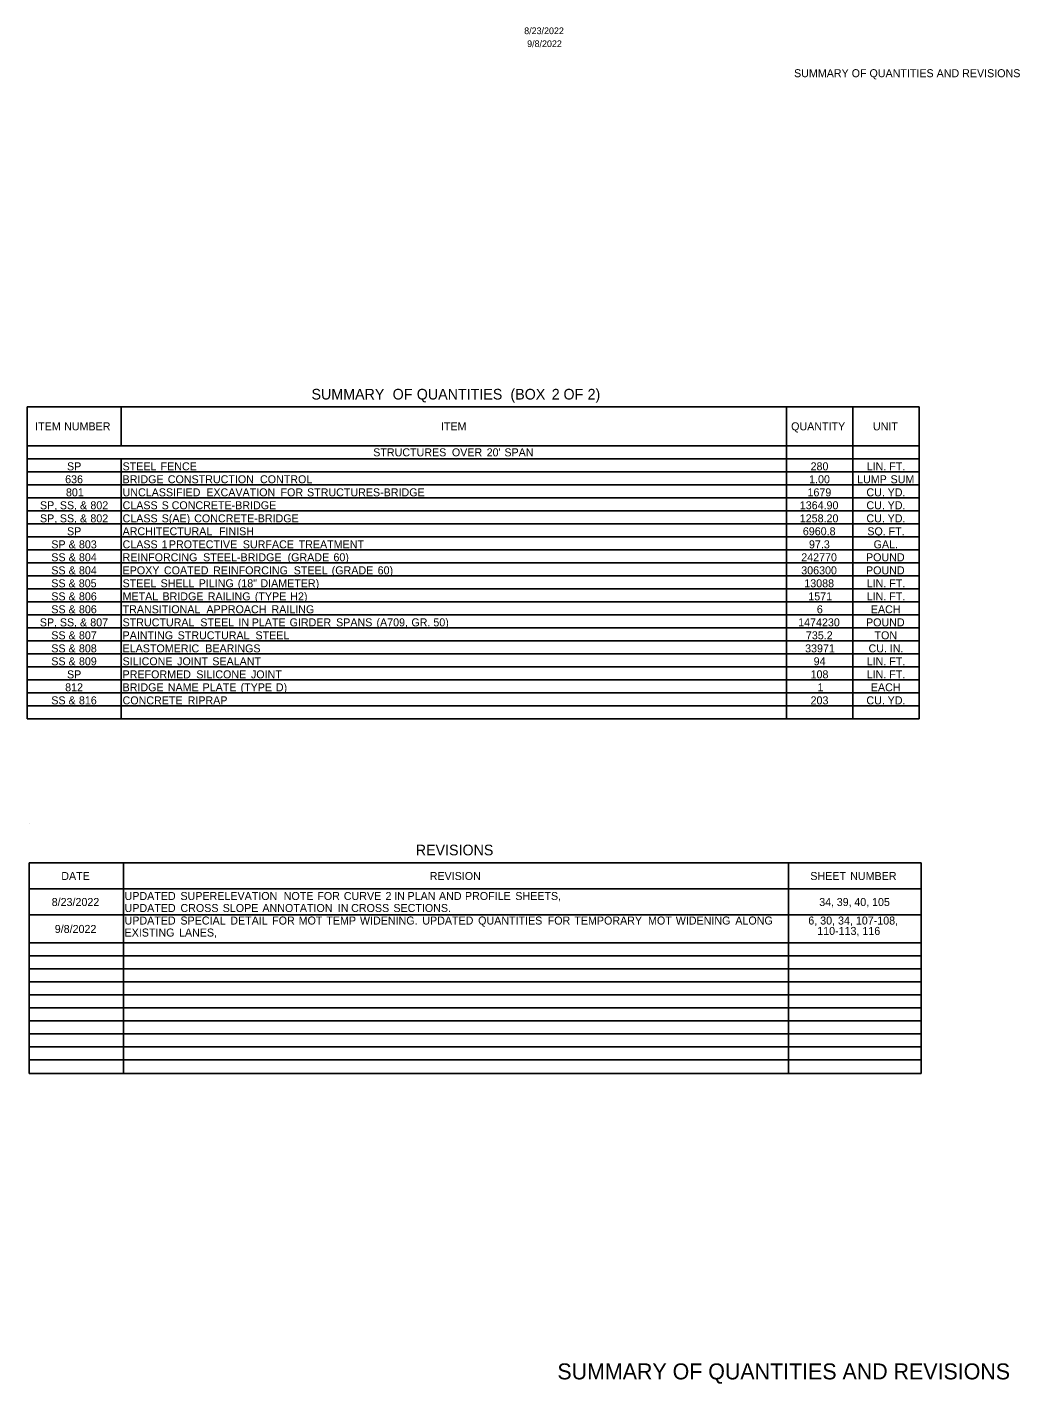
# Model space of a CAD drawing. Extents: x 1197542 to 1207068, y 230488 to 237324.
# Drawn here: x 1206323 to 1207068, y 231726 to 232744 of the extents above; entities that cross this region are included whole.
import ezdxf

# ---------------------------------------------------------------- set-up
doc = ezdxf.new("R2010")
doc.units = 0
for name, color, linetype in [('Default', 7, 'Continuous'), ('R_Annotation', 7, 'Continuous'), ('R_Border', 7, 'Continuous')]:
    doc.layers.add(name, color=color, linetype=linetype)

msp = doc.modelspace()

# ---------------------------------------------------------------- linework, layer by layer
at = {"layer": 'Default'}
for p, q in [((1206323.2, 232458.8), (1206393.8, 232458.8)), ((1206323.2, 232458.8), (1206992.5, 232458.8)), ((1206323.2, 232224.8), (1206323.2, 232458.8)), ((1206323.2, 232224.8), (1206323.2, 232458.8)), ((1206393.8, 232429.5), (1206393.8, 232458.8)), ((1206893, 232224.8), (1206893, 232458.8)), ((1206942.8, 232224.8), (1206942.8, 232458.8)), ((1206942.8, 232429.5), (1206942.8, 232458.8)), ((1206992.5, 232224.8), (1206992.5, 232458.8)), ((1206323.2, 232429.5), (1206992.5, 232429.5)), ((1206323.2, 232419.8), (1206992.5, 232419.8)), ((1206323.2, 232419.8), (1206992.5, 232419.8)), ((1206393.8, 232224.8), (1206393.8, 232419.8)), ((1206893, 232224.8), (1206893, 232419.8)), ((1206942.8, 232224.8), (1206942.8, 232419.8)), ((1206992.5, 232224.8), (1206992.5, 232419.8)), ((1206323.2, 232410), (1206992.5, 232410)), ((1206323.2, 232400.3), (1206992.5, 232400.3)), ((1206323.2, 232390.5), (1206992.5, 232390.5)), ((1206323.2, 232380.8), (1206992.5, 232380.8)), ((1206323.2, 232371), (1206992.5, 232371)), ((1206323.2, 232361.3), (1206992.5, 232361.3)), ((1206323.2, 232351.5), (1206992.5, 232351.5)), ((1206323.2, 232341.8), (1206992.5, 232341.8)), ((1206323.2, 232332), (1206992.5, 232332)), ((1206323.2, 232322.3), (1206992.5, 232322.3)), ((1206323.2, 232312.5), (1206992.5, 232312.5)), ((1206323.2, 232302.8), (1206992.5, 232302.8)), ((1206323.2, 232293), (1206992.5, 232293)), ((1206323.2, 232283.3), (1206992.5, 232283.3)), ((1206323.2, 232273.5), (1206992.5, 232273.5)), ((1206323.2, 232263.8), (1206992.5, 232263.8)), ((1206323.2, 232254), (1206992.5, 232254)), ((1206323.2, 232244.3), (1206992.5, 232244.3)), ((1206323.2, 232234.5), (1206992.5, 232234.5)), ((1206323.2, 232224.8), (1206992.5, 232224.8)), ((1206324.7, 232146), (1206324.7, 232146)), ((1206324.7, 232116.8), (1206994, 232116.8)), ((1206324.7, 232116.8), (1206395.4, 232116.8)), ((1206324.7, 231958.8), (1206324.7, 232116.8)), ((1206395.4, 231958.8), (1206395.4, 232116.8)), ((1206894.6, 232116.8), (1206994, 232116.8)), ((1206894.6, 232097.3), (1206894.6, 232116.8)), ((1206894.6, 231958.8), (1206894.6, 232116.8)), ((1206994, 231958.8), (1206994, 232116.8)), ((1206994, 231958.8), (1206994, 232116.8)), ((1206324.7, 232097.3), (1206994, 232097.3)), ((1206324.7, 232077.8), (1206994, 232077.8)), ((1206324.7, 232056.8), (1206994, 232056.8)), ((1206324.7, 232047.1), (1206994, 232047.1)), ((1206324.7, 232037.3), (1206994, 232037.3)), ((1206324.7, 232027.6), (1206994, 232027.6)), ((1206324.7, 232017.8), (1206994, 232017.8)), ((1206324.7, 232008.1), (1206994, 232008.1)), ((1206324.7, 231998.3), (1206994, 231998.3)), ((1206324.7, 231988.6), (1206994, 231988.6)), ((1206324.7, 231978.8), (1206994, 231978.8)), ((1206324.7, 231969.1), (1206994, 231969.1)), ((1206324.7, 231958.8), (1206994, 231958.8))]:
    msp.add_line(p, q, dxfattribs=at)

# ---------------------------------------------------------------- texts
for s, height, p in [(' SUMMARY', 8, (1206533.6, 232464.3)), (' OF', 8, (1206594.5, 232464.3)), (' QUANTITIES', 8, (1206612.6, 232464.3)), (' (BOX', 8, (1206682.9, 232464.3)), (' 2', 8, (1206713.9, 232464.3)), (' OF', 8, (1206722.7, 232464.3)), (' 2)', 8, (1206740.8, 232464.3)), ('ITEM', 6, (1206329.2, 232441.2)), (' NUMBER', 6, (1206348.7, 232441.2)), ('ITEM', 6, (1206633.7, 232441.2)), ('QUANTITY', 6, (1206896.5, 232441.2)), ('UNIT', 6, (1206957.9, 232441.2)), ('STRUCTURES', 6, (1206582.9, 232421.7)), (' OVER', 6, (1206639.7, 232421.7)), (" 20'", 6, (1206665.8, 232421.7)), (' SPAN', 6, (1206679.1, 232421.7)), ('SP', 6, (1206353.1, 232411.2)), ('STEEL', 6, (1206394.8, 232411.2)), (' FENCE', 6, (1206421.1, 232411.2)), ('280', 6, (1206911.1, 232411.2)), ('LIN.', 6, (1206953.2, 232411.2)), (' FT.', 6, (1206967.9, 232411.2)), ('636', 6, (1206351.7, 232401.5)), ('BRIDGE', 6, (1206394.8, 232401.5)), (' CONSTRUCTION', 6, (1206426.5, 232401.5)), (' CONTROL', 6, (1206495.7, 232401.5)), ('1.00', 6, (1206910, 232401.5)), ('LUMP', 6, (1206946, 232401.5)), (' SUM', 6, (1206968.9, 232401.5)), ('801', 6, (1206352.3, 232391.7)), ('UNCLASSIFIED', 6, (1206394.8, 232391.7)), (' EXCAVATION', 6, (1206455.4, 232391.7)), (' FOR', 6, (1206511.1, 232391.7)), (' STRUCTURES-BRIDGE', 6, (1206531, 232391.7)), ('1679', 6, (1206908.8, 232391.7)), ('CU.', 6, (1206953, 232391.7)), (' YD.', 6, (1206966.7, 232391.7)), ('SP,', 6, (1206332.8, 232382)), (' SS,', 6, (1206345.5, 232382)), (' &', 6, (1206360.6, 232382)), (' 802', 6, (1206368.4, 232382)), ('CLASS', 6, (1206394.8, 232382)), (' S', 6, (1206421.9, 232382)), (' CONCRETE-BRIDGE', 6, (1206429.4, 232382)), ('1364.90', 6, (1206903, 232382)), ('CU.', 6, (1206953, 232382)), (' YD.', 6, (1206966.7, 232382)), ('SP,', 6, (1206332.8, 232372.2)), (' SS,', 6, (1206345.5, 232372.2)), (' &', 6, (1206360.6, 232372.2)), (' 802', 6, (1206368.4, 232372.2)), ('CLASS', 6, (1206394.8, 232372.2)), (' S(AE)', 6, (1206421.9, 232372.2)), (' CONCRETE-BRIDGE', 6, (1206446.3, 232372.2)), ('1258.20', 6, (1206903, 232372.2)), ('CU.', 6, (1206953, 232372.2)), (' YD.', 6, (1206966.7, 232372.2)), ('SP', 6, (1206353.1, 232362.5)), ('ARCHITECTURAL', 6, (1206394.8, 232362.5)), (' FINISH', 6, (1206464.9, 232362.5)), ('6960.8', 6, (1206905.3, 232362.5)), ('SQ.', 6, (1206953.7, 232362.5)), (' FT.', 6, (1206967.4, 232362.5)), ('SP', 6, (1206341.3, 232352.7)), (' &', 6, (1206352.1, 232352.7)), (' 803', 6, (1206359.8, 232352.7)), ('CLASS', 6, (1206394.8, 232352.7)), (' 1', 6, (1206421.9, 232352.7)), (' PROTECTIVE', 6, (1206427.3, 232352.7)), (' SURFACE', 6, (1206482.8, 232352.7)), (' TREATMENT', 6, (1206524.7, 232352.7)), ('97.3', 6, (1206909.9, 232352.7)), ('GAL.', 6, (1206958.4, 232352.7)), ('SS', 6, (1206341.3, 232343)), (' &', 6, (1206352.1, 232343)), (' 804', 6, (1206359.8, 232343)), ('REINFORCING', 6, (1206394.8, 232343)), (' STEEL-BRIDGE', 6, (1206453, 232343)), (' (GRADE', 6, (1206516.4, 232343)), (' 60)', 6, (1206550.8, 232343)), ('242770', 6, (1206904.1, 232343)), ('POUND', 6, (1206952.7, 232343)), ('SS', 6, (1206341.3, 232333.2)), (' &', 6, (1206352.1, 232333.2)), (' 804', 6, (1206359.8, 232333.2)), ('EPOXY', 6, (1206394.8, 232333.2)), (' COATED', 6, (1206423.6, 232333.2)), (' REINFORCING', 6, (1206460.5, 232333.2)), (' STEEL', 6, (1206521, 232333.2)), (' (GRADE', 6, (1206549.5, 232333.2)), (' 60)', 6, (1206584, 232333.2)), ('306300', 6, (1206904.1, 232333.2)), ('POUND', 6, (1206952.7, 232333.2)), ('SS', 6, (1206341.3, 232323.5)), (' &', 6, (1206352, 232323.5)), (' 805', 6, (1206359.7, 232323.5)), ('STEEL', 6, (1206394.8, 232323.5)), (' SHELL', 6, (1206421.1, 232323.5)), (' PILING', 6, (1206449.7, 232323.5)), (' (18"', 6, (1206479, 232323.5)), (' DIAMETER)', 6, (1206496, 232323.5)), ('13088', 6, (1206906.4, 232323.5)), ('LIN.', 6, (1206953.2, 232323.5)), (' FT.', 6, (1206967.9, 232323.5)), ('SS', 6, (1206341.3, 232313.7)), (' &', 6, (1206352, 232313.7)), (' 806', 6, (1206359.8, 232313.7)), ('METAL', 6, (1206394.8, 232313.7)), (' BRIDGE', 6, (1206422.5, 232313.7)), (' RAILING', 6, (1206456.5, 232313.7)), (' (TYPE', 6, (1206491.8, 232313.7)), (' H2)', 6, (1206518.4, 232313.7)), ('1571', 6, (1206909.4, 232313.7)), ('LIN.', 6, (1206953.2, 232313.7)), (' FT.', 6, (1206967.9, 232313.7)), ('SS', 6, (1206341.3, 232304)), (' &', 6, (1206352, 232304)), (' 806', 6, (1206359.8, 232304)), ('TRANSITIONAL', 6, (1206394.8, 232304)), (' APPROACH', 6, (1206455.5, 232304)), (' RAILING', 6, (1206504.3, 232304)), ('6', 6, (1206915.8, 232304)), ('EACH', 6, (1206956.3, 232304)), ('SP,', 6, (1206332.7, 232294.2)), (' SS,', 6, (1206345.5, 232294.2)), (' &', 6, (1206360.6, 232294.2)), (' 807', 6, (1206368.3, 232294.2)), ('STRUCTURAL', 6, (1206394.8, 232294.2)), (' STEEL', 6, (1206450.9, 232294.2)), (' IN', 6, (1206479.5, 232294.2)), (' PLATE', 6, (1206489.5, 232294.2)), (' GIRDER', 6, (1206517.9, 232294.2)), (' SPANS', 6, (1206552.8, 232294.2)), (' (A709,', 6, (1206583.1, 232294.2)), (' GR.', 6, (1206609.3, 232294.2)), (' 50)', 6, (1206625.8, 232294.2)), ('1474230', 6, (1206901.8, 232294.2)), ('POUND', 6, (1206952.7, 232294.2)), ('SS', 6, (1206341.3, 232284.5)), (' &', 6, (1206352, 232284.5)), (' 807', 6, (1206359.8, 232284.5)), ('PAINTING', 6, (1206394.8, 232284.5)), (' STRUCTURAL', 6, (1206433.9, 232284.5)), (' STEEL', 6, (1206492.3, 232284.5)), ('735.2', 6, (1206907.6, 232284.5)), ('TON', 6, (1206959.1, 232284.5)), ('SS', 6, (1206341.3, 232274.7)), (' &', 6, (1206352, 232274.7)), (' 808', 6, (1206359.8, 232274.7)), ('ELASTOMERIC', 6, (1206394.8, 232274.7)), (' BEARINGS', 6, (1206454.6, 232274.7)), ('33971', 6, (1206907, 232274.7)), ('CU.', 6, (1206954.6, 232274.7)), (' IN.', 6, (1206968.3, 232274.7)), ('SS', 6, (1206341.3, 232265)), (' &', 6, (1206352, 232265)), (' 809', 6, (1206359.8, 232265)), ('SILICONE', 6, (1206394.8, 232265)), (' JOINT', 6, (1206433.5, 232265)), (' SEALANT', 6, (1206459.9, 232265)), ('94', 6, (1206913.4, 232265)), ('LIN.', 6, (1206953.2, 232265)), (' FT.', 6, (1206967.9, 232265)), ('812', 6, (1206351.7, 232245.5)), ('SP', 6, (1206353.1, 232255.2)), ('PREFORMED', 6, (1206394.8, 232255.2)), ('BRIDGE', 6, (1206394.8, 232245.5)), (' SILICONE', 6, (1206447.9, 232255.2)), (' (TYPE', 6, (1206481.1, 232245.5)), (' JOINT', 6, (1206488.9, 232255.2)), (' D)', 6, (1206507.6, 232245.5)), ('108', 6, (1206911.1, 232255.2)), ('LIN.', 6, (1206953.2, 232255.2)), ('EACH', 6, (1206956.3, 232245.5)), (' FT.', 6, (1206967.9, 232255.2)), ('SS', 6, (1206341.3, 232235.7)), (' &', 6, (1206352, 232235.7)), (' 816', 6, (1206359.8, 232235.7)), ('CONCRETE', 6, (1206394.8, 232235.7)), (' NAME', 6, (1206426.5, 232245.5)), (' RIPRAP', 6, (1206441.4, 232235.7)), (' PLATE', 6, (1206452.6, 232245.5)), ('203', 6, (1206911.1, 232235.7)), ('1', 6, (1206916.3, 232245.5)), ('CU.', 6, (1206953, 232235.7)), (' YD.', 6, (1206966.7, 232235.7)), ('REVISIONS', 8, (1206614.8, 232122.5)), ('DATE', 6, (1206348.8, 232104)), ('REVISION', 6, (1206625.3, 232104)), ('SHEET', 6, (1206910.9, 232104)), (' NUMBER', 6, (1206938.6, 232104)), ('8/23/2022', 6, (1206341.6, 232084.5)), ('UPDATED', 6, (1206396.3, 232089)), (' SUPERELEVATION', 6, (1206436, 232089)), (' NOTE', 6, (1206513.5, 232089)), (' FOR', 6, (1206538.7, 232089)), (' CURVE', 6, (1206558.6, 232089)), (' 2', 6, (1206589.9, 232089)), (' IN', 6, (1206596.4, 232089)), (' PLAN', 6, (1206606.4, 232089)), (' AND', 6, (1206630, 232089)), (' PROFILE', 6, (1206649.5, 232089)), (' SHEETS,', 6, (1206687.3, 232089)), ('34,', 6, (1206917.6, 232084.5)), (' 39,', 6, (1206928.5, 232084.5)), (' 40,', 6, (1206941.7, 232084.5)), (' 105', 6, (1206955, 232084.5)), ('UPDATED', 6, (1206396.3, 232080)), (' CROSS', 6, (1206436, 232080)), (' SLOPE', 6, (1206467.7, 232080)), (' ANNOTATION', 6, (1206497.5, 232080)), (' IN', 6, (1206554.1, 232080)), (' CROSS', 6, (1206564.1, 232080)), (' SECTIONS.', 6, (1206595.8, 232080)), ('9/8/2022', 6, (1206343.9, 232064.3)), ('UPDATED', 6, (1206396.3, 232070.6)), (' SPECIAL', 6, (1206436, 232070.6)), (' DETAIL', 6, (1206473.4, 232070.6)), (' FOR', 6, (1206504.8, 232070.6)), (' MOT', 6, (1206524.7, 232070.6)), (' TEMP', 6, (1206545.5, 232070.6)), (' WIDENING.', 6, (1206570.7, 232070.6)), (' UPDATED', 6, (1206617.5, 232070.6)), (' QUANTITIES', 6, (1206659.4, 232070.6)), (' FOR', 6, (1206711.6, 232070.6)), (' TEMPORARY', 6, (1206731.6, 232070.6)), (' MOT', 6, (1206786.9, 232070.6)), (' WIDENING', 6, (1206807.7, 232070.6)), (' ALONG', 6, (1206852.4, 232070.6)), ('6, 30, 34, 107-108, ', 6, (1206909.4, 232070.6)), ('   110-113, 116', 6, (1206909.4, 232062.8)), ('EXISTING', 6, (1206396.3, 232061.6)), (' LANES,', 6, (1206434.9, 232061.6))]:
    msp.add_text(s, height=height, dxfattribs=at).set_placement(p)
at = {"layer": 'R_Annotation'}
msp.add_text('SUMMARY OF QUANTITIES AND REVISIONS', height=12, rotation=360, dxfattribs=at).set_placement((1206721.1, 231729.5))
at = {"layer": 'R_Border'}
for s, height, p in [('8/23/2022', 5, (1206696.2, 232738.3)), ('9/8/2022', 5, (1206698.4, 232728.6)), ('SUMMARY OF QUANTITIES AND REVISIONS', 6, (1206898.7, 232706))]:
    msp.add_text(s, height=height, rotation=360, dxfattribs=at).set_placement(p)

doc.saveas('drawing.dxf')
